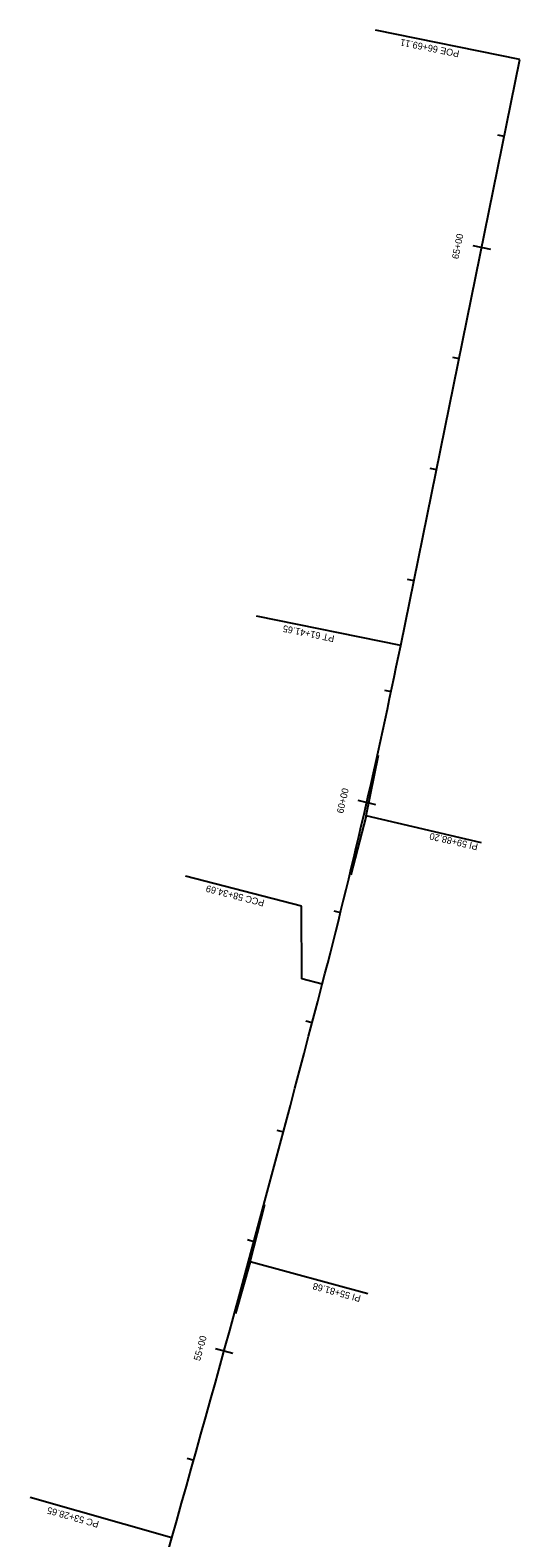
# Model space of a CAD drawing. Extents: x 1445613 to 1446340, y 2043492 to 2056486.
# Drawn here: x 1445908 to 1446340, y 2055156 to 2056486 of the extents above; entities that cross this region are included whole.
import ezdxf

# ---------------------------------------------------------------- set-up
doc = ezdxf.new("R2010")
doc.units = 0
for name, color, linetype in [('R_Horz Alg', 7, 'Continuous'), ('R_Horz Alg Annot', 7, 'Continuous'), ('R_Horz Alg Annot_Detour', 7, 'Continuous'), ('R_Horz Alg Stationing_Detour', 7, 'Continuous')]:
    doc.layers.add(name, color=color, linetype=linetype)

msp = doc.modelspace()

# ---------------------------------------------------------------- linework, layer by layer
at = {"layer": 'R_Horz Alg'}
for p, q in [((1446235.1, 2055943), (1446340.2, 2056459.8)), ((1445909.6, 2054720), (1446033.2, 2055155.6))]:
    msp.add_line(p, q, dxfattribs=at)
for centre, radius, start, end in [((1440620.5, 2057085.3), 5729.6, 345.4304, 348.5), ((1423960.8, 2061415.4), 22942.8, 344.16667, 345.4304)]:
    msp.add_arc(centre, radius, start, end, dxfattribs=at)
at = {"layer": 'R_Horz Alg Annot'}
for p, q in [((1446204.5, 2055792.5), (1446215.4, 2055846.1)), ((1446204.5, 2055792.5), (1446191, 2055740.7)), ((1446306.4, 2055768.9), (1446204.5, 2055792.5)), ((1446102.2, 2055399.1), (1446115.3, 2055449.7)), ((1446102.2, 2055399.1), (1446089.3, 2055353.7)), ((1446206.1, 2055370.8), (1446102.2, 2055399.1))]:
    msp.add_line(p, q, dxfattribs=at)
at = {"layer": 'R_Horz Alg Annot_Detour'}
msp.add_line((1446147.7, 2055648.7), (1446147.5, 2055712.8), dxfattribs=at)
for points in [[(1446340.2, 2056459.8), (1446212.8, 2056485.8)], [(1446235.1, 2055943), (1446107.7, 2055968.9)], [(1446147.5, 2055712.8), (1446045.1, 2055739.5)], [(1446165.8, 2055644), (1446147.7, 2055648.7)], [(1446033.2, 2055155.6), (1445908.1, 2055191.1)]]:
    msp.add_lwpolyline(points, dxfattribs=at)
at = {"layer": 'R_Horz Alg Stationing_Detour'}
for points in [[(1446320.6, 2056393.3), (1446326.4, 2056392.1)], [(1446298.7, 2056295.7), (1446314.3, 2056292.5)], [(1446280.7, 2056197.3), (1446286.6, 2056196.1)], [(1446260.8, 2056099.3), (1446266.6, 2056098.1)], [(1446240.8, 2056001.3), (1446246.7, 2056000.2)], [(1446220.7, 2055903.4), (1446226.6, 2055902.2)], [(1446197.3, 2055806.3), (1446212.9, 2055802.7)], [(1446176.1, 2055708.7), (1446181.9, 2055707.3)], [(1446151.3, 2055611.9), (1446157.1, 2055610.4)], [(1446125.8, 2055515.2), (1446131.6, 2055513.7)], [(1446099.9, 2055418.7), (1446105.6, 2055417.1)], [(1446071.6, 2055322.8), (1446087, 2055318.5)], [(1446046.7, 2055225.9), (1446052.5, 2055224.3)]]:
    msp.add_lwpolyline(points, dxfattribs=at)

# ---------------------------------------------------------------- texts
at = {"layer": 'R_Horz Alg Annot_Detour'}
for s, rotation, p in [('POE 66+69.11', 168.5, (1446287.2, 2056467.6)), ('PT 61+41.65', 168.5, (1446177, 2055951.7)), ('PI 59+88.20', 167.1077, (1446303.7, 2055768)), ('PCC 58+34.69', 165.4304, (1446115.3, 2055718.3)), ('PI 55+81.68', 164.765, (1446200.4, 2055369.4)), ('PC 53+28.65', 164.1667, (1445969.3, 2055170.2))]:
    msp.add_text(s, height=6, rotation=rotation, dxfattribs=at).set_placement(p)
at = {"layer": 'R_Horz Alg Stationing_Detour'}
for s, rotation, p in [('65+00', 78.5, (1446286, 2056283.4)), ('60+00', 77.0835, (1446184.3, 2055794.3)), ('55+00', 74.5946, (1446058, 2055311.3))]:
    msp.add_text(s, height=6, rotation=rotation, dxfattribs=at).set_placement(p)

doc.saveas('drawing.dxf')
